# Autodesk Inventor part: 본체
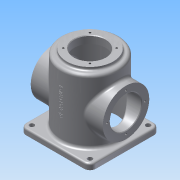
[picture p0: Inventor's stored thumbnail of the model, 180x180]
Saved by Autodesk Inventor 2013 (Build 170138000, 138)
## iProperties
Created: 2015-10
Part Number: 본체
Material: 알루미늄 6061
Document SubType Name: Modeling
Designer: Administrator
Density: 2.71 g/cm^3
Mass: 985.997 g
Surface Area: 1037.35 cm^2
Volume: 363.836 cm^3
Author: Administrator
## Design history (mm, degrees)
sketch "스케치1"
  geometry: L1 (-50, 60)-(50, 60); L2 (60, 50)-(60, -50); L3 (50, -60)-(-50, -60); L4 (-60, -50)-(-60, 50); A1 r 10 centre (-50, 50) between (-50, 60) and (-60, 50); A2 r 10 centre (-50, -50) between (-60, -50) and (-50, -60); A3 r 10 centre (50, -50) between (50, -60) and (60, -50); A4 r 10 centre (50, 50) between (60, 50) and (50, 60); 5 further points
  constraints: 8 end point, 8 point on circle, 8 tangent, 4 centre point, 4 point on line, 3 equal radius, 2 midpoint, 2 parallel, 2 perpendicular, 1 horizontal, 1 horizontal alignment, 1 vertical alignment
  dimensions: "d0" = 120 distance of point (-60, 60) point (60, 60); "d2" = 10 radius of A1
extrude "돌출1" new body sketch "스케치1" distance "d4" = 10; taper "d5" = 0 deg
sketch "스케치2"
  geometry: C1 r 50 at (0, 0); 1 further point
  constraints: 1 centre point, 1 coincident
  dimensions: "d6" = 100 diameter of C1
extrude "돌출2" join sketch "스케치2" distance "d8" = 110; taper "d9" = 0 deg
sketch "스케치3"
  geometry: C1 r 40 at (0, 0); 1 further point
  constraints: 1 centre point, 1 coincident
  dimensions: "d10" = 80 diameter of C1
extrude "돌출3" join sketch "스케치3" distance "d12" = 5; taper "d13" = 0 deg
sketch "스케치4"
  geometry: C1 r 40 at (0, 60); 1 further point
  constraints: 1 centre point, 1 vertical alignment
  dimensions: "d14" = 80 diameter of C1; "d16" = 60 distance of C1.centre point (0, 0)
extrude "돌출4" join sketch "스케치4" stored distance "d17" = 124; taper "d18" = 0 deg
hole "구멍1" diameter "d21" = 54; stored, may be unused: countersink angle "d25" = 90 deg, drill point angle "d27" = 118 deg; dims "d19" = 10, "d20" = 10, "d22" = 6, "d23" = 90, "d24" = 112, "d26" = 8
hole "구멍2" diameter "d30" = 54; stored, may be unused: countersink angle "d34" = 90 deg, drill point angle "d36" = 118 deg; dims "d28" = 10, "d29" = 10, "d31" = 6, "d32" = 90, "d33" = 112, "d35" = 8
sketch "스케치5"
  geometry: C1 r 27 at (0, 0) reference; 2 further points
  constraints: 1 horizontal alignment
  dimensions: "d37" = 32.5 distance of point (32.5, 0) C1.centre
hole "구멍3" sketch "스케치5" at (32.5, 0) diameter "d38" = 3.242; stored, may be unused: countersink angle "d42" = 90 deg, drill point angle "d44" = 118 deg; dims "d39" = 8, "d40" = 90, "d41" = 112, "d43" = 10
sketch "스케치6"
  geometry: A1 r 32.5 centre (0, 0) between (-22.981, 22.981) and (22.981, 22.981); 3 further points
  constraints: 4 point on circle, 2 horizontal alignment, 2 vertical alignment, 1 centre point, 1 coincident
  dimensions: "d48" = 65 diameter of A1; "d49" = 90 deg dimension on point (0, 0) A1.end A1.start
hole "구멍4" sketch "스케치6" at (-22.981, 22.981), (22.981, 22.981), (22.981, -22.981), (-22.981, -22.981) diameter "d51" = 3.242; stored, may be unused: countersink angle "d55" = 90 deg, drill point angle "d57" = 118 deg; dims "d52" = 8, "d53" = 90, "d54" = 112, "d56" = 10
hole "구멍5" diameter "d60" = 8; stored, may be unused: countersink angle "d64" = 90 deg, drill point angle "d66" = 0 deg; dims "d58" = 10, "d59" = 10, "d61" = 8, "d62" = 90, "d63" = 112, "d65" = 20
hole "구멍6" diameter "d69" = 8; stored, may be unused: countersink angle "d73" = 90 deg, drill point angle "d75" = 0 deg; dims "d67" = 10, "d68" = 10, "d70" = 8, "d71" = 90, "d72" = 112, "d74" = 20
hole "구멍7" diameter "d78" = 8; stored, may be unused: countersink angle "d82" = 90 deg, drill point angle "d84" = 0 deg; dims "d76" = 10, "d77" = 10, "d79" = 8, "d80" = 90, "d81" = 112, "d83" = 20
hole "구멍8" diameter "d87" = 8; stored, may be unused: countersink angle "d91" = 90 deg, drill point angle "d93" = 0 deg; dims "d85" = 10, "d86" = 10, "d88" = 8, "d89" = 90, "d90" = 112, "d92" = 20
node "작업 평면1"
sketch "스케치7"
  geometry: L1 (-3.602, 31.245)-(-3.602, 88.755); L2 (-3.602, 88.755)-(3.602, 88.755); L3 (3.602, 88.755)-(3.602, 31.245); L4 (3.602, 31.245)-(-3.602, 31.245); L5 (-50, -10)-(50, -10) reference; 5 further points
  constraints: 3 midpoint, 2 vertical alignment, 1 horizontal alignment, 2 other
  dimensions: "d105" = 70 distance of point (0, 60) point (0, -10)
feature "엠보싱1" sketch "스케치7" dims "d0" = 120, "d2" = 10, "d94" = 0.5, "d95" = 0
chamfer "모따기1" distance "d96" = 3; stored, may be unused: second distance "d97" = 2, angle "d98" = 45 deg
chamfer "모따기2" distance "d99" = 1; stored, may be unused: second distance "d100" = 2, angle "d101" = 45 deg
fillet "모깎기4" dims "d106" = 5
fillet "모깎기5" dims "d107" = 5
fillet "모깎기6" dims "d108" = 3
fillet "모깎기2" dims "d103" = 3
fillet "모깎기3" dims "d104" = 3
fillet "모깎기7" dims "d109" = 3
node "솔리드1"
pattern_circular "원형 패턴1" dims angle "d46" = 360 deg
mirror "대칭1"
